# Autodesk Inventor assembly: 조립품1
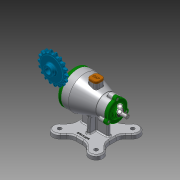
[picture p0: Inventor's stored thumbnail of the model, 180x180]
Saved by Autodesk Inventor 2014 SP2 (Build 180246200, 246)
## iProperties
Created: 2018-03
Part Number: 조립품1
Document SubType Name: Assembly
Designer: 거성
Author: 거성
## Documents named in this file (15)
- C:\Users\거성\Desktop\480308V1008\조립품1.iam
- C:\Users\거성\Desktop\480308V1008\본체.ipt
- C:\Users\거성\Desktop\480308V1008\뒤커버.ipt
- C:\Users\거성\Desktop\480308V1008\마개.ipt
- C:\Users\거성\Desktop\480308V1008\베어링-6200.ipt
- C:\Users\거성\Desktop\480308V1008\베어링-6203.ipt
- C:\Users\거성\Desktop\480308V1008\볼트 M4 x 12.ipt
- 볼트 M4 x 12.ipt
- C:\Users\거성\Desktop\480308V1008\스프로킷.ipt
- C:\Users\거성\Desktop\480308V1008\앞커버.ipt
- C:\Users\거성\Desktop\480308V1008\오일 실 10 20 7.ipt
- C:\Users\거성\Desktop\480308V1008\오일 실 17 30 8.ipt
- C:\Users\거성\Desktop\480308V1008\축.ipt
- C:\Users\거성\Desktop\480308V1008\키 5 x 5.ipt
- 키 5 x 5.ipt
